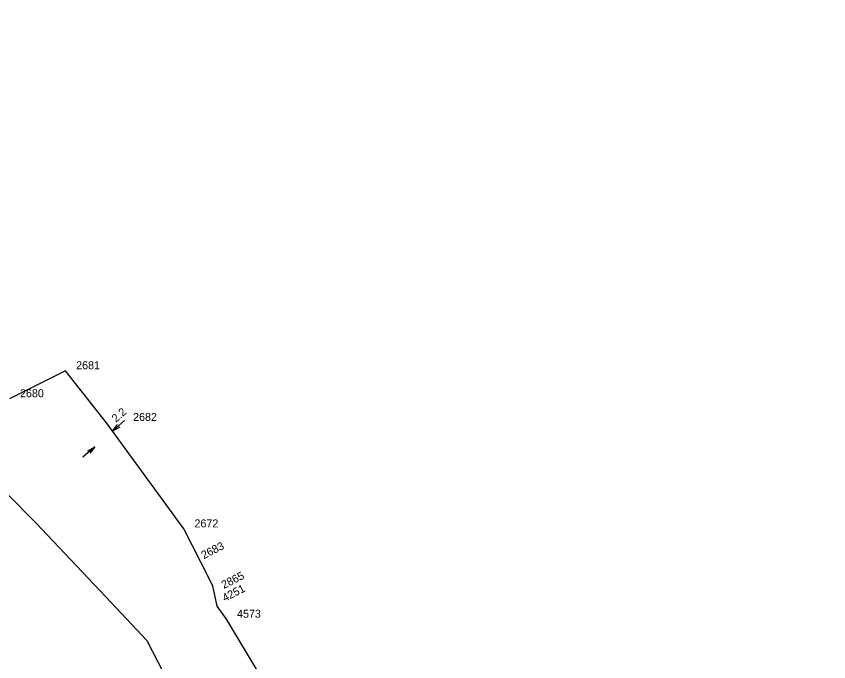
# Model space of a CAD drawing. Extents: x -535557 to -534097, y -1142175 to -1136716.
# Drawn here: x -535278.4 to -535202.3, y -1138530 to -1138469.4 of the extents above; entities that cross this region are included whole.
import ezdxf

# ---------------------------------------------------------------- set-up
doc = ezdxf.new("R2010")
doc.units = 0
for name, color, linetype in [('Default', 7, 'Continuous'), ('GIS_vektor_sdelovaci_kabely_CD', 7, 'Continuous'), ('SS_SZDC', 7, 'Continuous')]:
    doc.layers.add(name, color=color, linetype=linetype)

# ---------------------------------------------------------------- blocks, each defined once
blk = doc.blocks.new('POINT_DISPLAY')
at = {"layer": 'Default'}
blk.add_line((0, 0), (0, 0), dxfattribs=at)

msp = doc.modelspace()

# ---------------------------------------------------------------- linework, layer by layer
at = {"layer": 'GIS_vektor_sdelovaci_kabely_CD'}
msp.add_lwpolyline([(-535319.228, -1138468.225), (-535312.134, -1138477.681), (-535306.578, -1138482.264), (-535295.997, -1138494.75), (-535288.97, -1138503.271), (-535279.183, -1138514.276), (-535276.556, -1138516.936), (-535270.008, -1138523.859), (-535266.161, -1138527.963), (-535262.595, -1138534.859), (-535261.596, -1138536.721), (-535250.636, -1138550.535), (-535240.996, -1138561.428), (-535238.641, -1138562.108), (-535234.874, -1138566.378), (-535233.263, -1138567.105), (-535231.845, -1138569.165), (-535227.777, -1138573.592), (-535226.657, -1138576.911), (-535216.743, -1138588.55), (-535215.025, -1138590.318), (-535214.415, -1138590.897), (-535212.811, -1138593.077), (-535202.253, -1138605.902)], dxfattribs=at)
at = {"layer": 'SS_SZDC'}
for p, q in [((-535273.779, -1138502.68), (-535279.039, -1138505.309)), ((-535269.93, -1138507.549), (-535273.779, -1138502.68)), ((-535262.689, -1138517.51), (-535269.93, -1138507.549)), ((-535269.361, -1138508.331), (-535268.233, -1138507.342)), ((-535269.361, -1138508.331), (-535268.896, -1138507.724)), ((-535268.698, -1138507.95), (-535269.361, -1138508.331)), ((-535271.025, -1138509.791), (-535272.153, -1138510.78)), ((-535271.688, -1138510.172), (-535271.025, -1138509.791)), ((-535271.025, -1138509.791), (-535271.49, -1138510.398)), ((-535261.13, -1138520.559), (-535262.689, -1138517.51)), ((-535259.979, -1138522.85), (-535261.13, -1138520.559)), ((-535259.569, -1138524.739), (-535259.979, -1138522.85)), ((-535258.699, -1138525.979), (-535259.569, -1138524.739)), ((-535234.949, -1138565.37), (-535258.699, -1138525.979))]:
    msp.add_line(p, q, dxfattribs=at)

# ---------------------------------------------------------------- block references
for p in [(-535273.779, -1138502.68), (-535269.93, -1138507.549), (-535262.689, -1138517.51), (-535261.13, -1138520.559), (-535259.979, -1138522.85), (-535259.569, -1138524.739), (-535258.699, -1138525.979)]:
    msp.add_blockref('POINT_DISPLAY', p, dxfattribs=at)

# ---------------------------------------------------------------- texts
for s, p in [('2681', (-535272.779, -1138502.53)), ('2680', (-535278.039, -1138505.159)), ('2682', (-535267.443, -1138507.377)), ('2672', (-535261.69, -1138517.359)), ('4573', (-535257.699, -1138525.829))]:
    msp.add_text(s, height=0.75, dxfattribs=at).set_placement(p)
for s, rotation, p in [('2.2', 41.25075, (-535269.045, -1138507.555)), ('2683', 27, (-535260.819, -1138520.35)), ('2865', 27, (-535258.936, -1138523.138)), ('4251', 27, (-535258.853, -1138524.349))]:
    msp.add_text(s, height=0.75, rotation=rotation, dxfattribs=at).set_placement(p)

doc.saveas('drawing.dxf')
